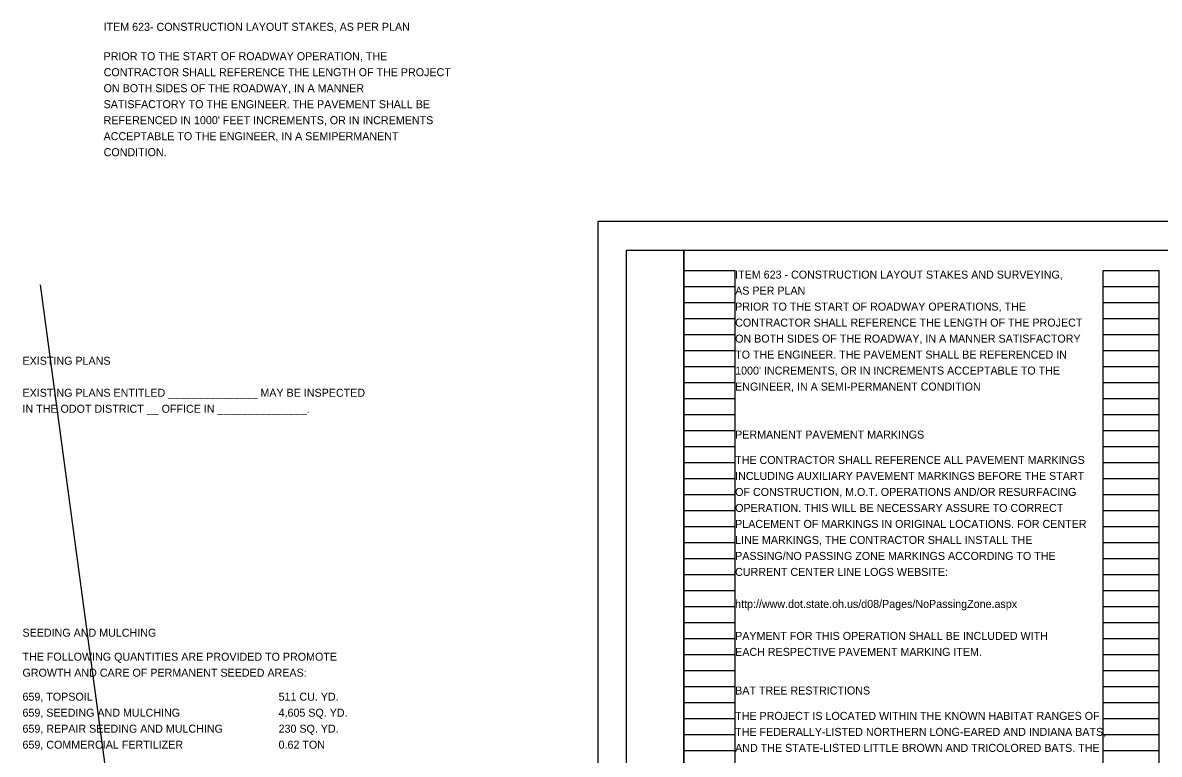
# Model space of a CAD drawing. Extents: x -10.1 to 44.3, y -20.7 to 25.5.
# Drawn here: x -10.06 to 9.82, y 12.67 to 25.48 of the extents above; entities that cross this region are included whole.
import ezdxf

# ---------------------------------------------------------------- set-up
doc = ezdxf.new("R2010")
doc.units = 0
for name, color, linetype in [('Default', 7, 'Continuous'), ('SH_Border', 7, 'Continuous'), ('SH_Cut_Line', 7, 'Continuous'), ('SH_Data', 7, 'Continuous'), ('SH_Text', 7, 'Continuous')]:
    doc.layers.add(name, color=color, linetype=linetype)

msp = doc.modelspace()

# ---------------------------------------------------------------- linework, layer by layer
at = {"layer": 'Default'}
msp.add_line((-9.759, 20.89), (-7.206, 1.966), dxfattribs=at)
at = {"layer": 'SH_Border'}
for points in [[(0.5, 21.5), (1.5, 21.5), (1.5, 0.5), (0.5, 0.5)], [(1.5, 21.5), (33.5, 21.5), (33.5, 0.5), (1.5, 0.5)]]:
    msp.add_lwpolyline(points, close=True, dxfattribs=at)
at = {"layer": 'SH_Cut_Line'}
msp.add_lwpolyline([(0, 0), (34, 0), (34, 22), (0, 22)], close=True, dxfattribs=at)
at = {"layer": 'SH_Data'}
for p, q in [((1.5, 0.98), (1.5, 21.14)), ((1.5, 21.14), (2.4, 21.14)), ((2.4, 0.98), (2.4, 21.14)), ((8.84, 0.98), (8.84, 21.14)), ((8.84, 21.14), (9.82, 21.14)), ((9.82, 0.98), (9.82, 21.14)), ((1.5, 20.86), (2.4, 20.86)), ((8.84, 20.86), (9.82, 20.86)), ((1.5, 20.58), (2.4, 20.58)), ((8.84, 20.58), (9.82, 20.58)), ((1.5, 20.3), (2.4, 20.3)), ((8.84, 20.3), (9.82, 20.3)), ((1.5, 20.02), (2.4, 20.02)), ((8.84, 20.02), (9.82, 20.02)), ((1.5, 19.74), (2.4, 19.74)), ((8.84, 19.74), (9.82, 19.74)), ((1.5, 19.46), (2.4, 19.46)), ((8.84, 19.46), (9.82, 19.46)), ((1.5, 19.18), (2.4, 19.18)), ((8.84, 19.18), (9.82, 19.18)), ((1.5, 18.9), (2.4, 18.9)), ((8.84, 18.9), (9.82, 18.9)), ((1.5, 18.62), (2.4, 18.62)), ((8.84, 18.62), (9.82, 18.62)), ((1.5, 18.34), (2.4, 18.34)), ((8.84, 18.34), (9.82, 18.34)), ((1.5, 18.06), (2.4, 18.06)), ((8.84, 18.06), (9.82, 18.06)), ((1.5, 17.78), (2.4, 17.78)), ((8.84, 17.78), (9.82, 17.78)), ((1.5, 17.5), (2.4, 17.5)), ((8.84, 17.5), (9.82, 17.5)), ((1.5, 17.22), (2.4, 17.22)), ((8.84, 17.22), (9.82, 17.22)), ((1.5, 16.94), (2.4, 16.94)), ((8.84, 16.94), (9.82, 16.94)), ((1.5, 16.66), (2.4, 16.66)), ((8.84, 16.66), (9.82, 16.66)), ((1.5, 16.38), (2.4, 16.38)), ((8.84, 16.38), (9.82, 16.38)), ((1.5, 16.1), (2.4, 16.1)), ((8.84, 16.1), (9.82, 16.1)), ((1.5, 15.82), (2.4, 15.82)), ((8.84, 15.82), (9.82, 15.82)), ((1.5, 15.54), (2.4, 15.54)), ((8.84, 15.54), (9.82, 15.54)), ((1.5, 15.26), (2.4, 15.26)), ((8.84, 15.26), (9.82, 15.26)), ((1.5, 14.98), (2.4, 14.98)), ((8.84, 14.98), (9.82, 14.98)), ((1.5, 14.7), (2.4, 14.7)), ((8.84, 14.7), (9.82, 14.7)), ((1.5, 14.42), (2.4, 14.42)), ((8.84, 14.42), (9.82, 14.42)), ((1.5, 14.14), (2.4, 14.14)), ((8.84, 14.14), (9.82, 14.14)), ((1.5, 13.86), (2.4, 13.86)), ((8.84, 13.86), (9.82, 13.86)), ((1.5, 13.58), (2.4, 13.58)), ((8.84, 13.58), (9.82, 13.58)), ((1.5, 13.3), (2.4, 13.3)), ((8.84, 13.3), (9.82, 13.3)), ((1.5, 13.02), (2.4, 13.02)), ((8.84, 13.02), (9.82, 13.02)), ((1.5, 12.74), (2.4, 12.74)), ((8.84, 12.74), (9.82, 12.74))]:
    msp.add_line(p, q, dxfattribs=at)

# ---------------------------------------------------------------- texts
at = {"layer": 'SH_Text'}
for s, p in [('ITEM 623- CONSTRUCTION LAYOUT STAKES, AS PER PLAN', (-8.649, 25.337)), ('PRIOR TO THE START OF ROADWAY OPERATION, THE', (-8.649, 24.823)), ('CONTRACTOR SHALL REFERENCE THE LENGTH OF THE PROJECT', (-8.649, 24.543)), ('ON BOTH SIDES OF THE ROADWAY, IN A MANNER', (-8.649, 24.263)), ('SATISFACTORY TO THE ENGINEER. THE PAVEMENT SHALL BE', (-8.649, 23.983)), ("REFERENCED IN 1000' FEET INCREMENTS, OR IN INCREMENTS", (-8.649, 23.703)), ('ACCEPTABLE TO THE ENGINEER, IN A SEMIPERMANENT', (-8.649, 23.423)), ('CONDITION.', (-8.649, 23.143)), ('ITEM 623 - CONSTRUCTION LAYOUT STAKES AND SURVEYING, ', (2.4, 21)), ('AS PER PLAN', (2.4, 20.72)), ('PRIOR TO THE START OF ROADWAY OPERATIONS, THE', (2.4, 20.44)), ('CONTRACTOR SHALL REFERENCE THE LENGTH OF THE PROJECT', (2.4, 20.16)), ('ON BOTH SIDES OF THE ROADWAY, IN A MANNER SATISFACTORY', (2.4, 19.88)), ('TO THE ENGINEER. THE PAVEMENT SHALL BE REFERENCED IN', (2.4, 19.6)), ('EXISTING PLANS', (-10.068, 19.492)), ("1000' INCREMENTS, OR IN INCREMENTS ACCEPTABLE TO THE", (2.4, 19.32)), ('ENGINEER, IN A SEMI-PERMANENT CONDITION', (2.4, 19.04)), ('EXISTING PLANS ENTITLED _______________ MAY BE INSPECTED', (-10.068, 18.932)), ('IN THE ODOT DISTRICT __ OFFICE IN _______________.', (-10.068, 18.652)), ('PERMANENT PAVEMENT MARKINGS', (2.4, 18.2)), ('THE CONTRACTOR SHALL REFERENCE ALL PAVEMENT MARKINGS', (2.4, 17.756)), ('INCLUDING AUXILIARY PAVEMENT MARKINGS BEFORE THE START', (2.4, 17.476)), ('OF CONSTRUCTION, M.O.T. OPERATIONS AND/OR RESURFACING', (2.4, 17.196)), ('OPERATION. THIS WILL BE NECESSARY ASSURE TO CORRECT ', (2.4, 16.916)), ('PLACEMENT OF MARKINGS IN ORIGINAL LOCATIONS. FOR CENTER', (2.4, 16.636)), ('LINE MARKINGS, THE CONTRACTOR SHALL INSTALL THE', (2.4, 16.356)), ('PASSING/NO PASSING ZONE MARKINGS ACCORDING TO THE', (2.4, 16.076)), ('CURRENT CENTER LINE LOGS WEBSITE:', (2.4, 15.796)), ('http://www.dot.state.oh.us/d08/Pages/NoPassingZone.aspx', (2.4, 15.236)), ('SEEDING AND MULCHING', (-10.068, 14.732)), ('PAYMENT FOR THIS OPERATION SHALL BE INCLUDED WITH', (2.4, 14.676)), ('EACH RESPECTIVE PAVEMENT MARKING ITEM.', (2.4, 14.396)), ('THE FOLLOWING QUANTITIES ARE PROVIDED TO PROMOTE', (-10.068, 14.312)), ('GROWTH AND CARE OF PERMANENT SEEDED AREAS:', (-10.068, 14.032)), ('659, TOPSOIL                      ', (-10.068, 13.612)), ('511 CU. YD.', (-5.588, 13.612)), ('BAT TREE RESTRICTIONS', (2.4, 13.72)), ('659, SEEDING AND MULCHING         ', (-10.068, 13.332)), ('4,605 SQ. YD.', (-5.588, 13.332)), ('THE PROJECT IS LOCATED WITHIN THE KNOWN HABITAT RANGES OF ', (2.4, 13.276)), ('659, REPAIR SEEDING AND MULCHING   ', (-10.068, 13.052)), ('230 SQ. YD.', (-5.588, 13.052)), ('THE FEDERALLY-LISTED NORTHERN LONG-EARED AND INDIANA BATS, ', (2.4, 12.996)), ('659, COMMERCIAL FERTILIZER         ', (-10.068, 12.772)), ('0.62 TON', (-5.588, 12.772)), ('AND THE STATE-LISTED LITTLE BROWN AND TRICOLORED BATS. THE ', (2.4, 12.716))]:
    msp.add_text(s, height=0.14, dxfattribs=at).set_placement(p)

doc.saveas('drawing.dxf')
